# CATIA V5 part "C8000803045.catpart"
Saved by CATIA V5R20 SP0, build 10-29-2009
Part number: C8000803045
Source: Unknown
Property "A": "50"
Property "ARTICLENO": "C8000803045"
Property "B": "23"
Property "BOMINFO": "C8000803045"
Property "C": "95"
Property "CA": "C8000803045"
Property "D1": "85"
Property "DES": "ROTATING EYEBOLT WITH RING Ton 8 M30x45"
Property "E": "95"
Property "H": "205"
Property "L": "45"
Property "LINA": "C8000803045"
Property "NB": "C8000803045"
Property "NBSYN": "$CODE."
Property "NN": "C800"
Property "NT": "Rotating eyebolt with ring"
Property "SIZE": "M30"
Property "SUPPLIER": "CF"
Property "SW": "75"
Property "WEIGHT": "5300"
Property "WLL": "8.00"
Bounding box of the stored display mesh (mm): x -47.825 to 48, y -45 to 227.825, z -42.5 to 42.5
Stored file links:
  C:\Users\Utente\Desktop\3D files 800\C8000803045.catpart
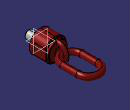
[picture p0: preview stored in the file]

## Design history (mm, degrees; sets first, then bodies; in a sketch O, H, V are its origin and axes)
Body1 "Geometry.1" (main body)
  Solid1 "C8000803045.catpart": solid without history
